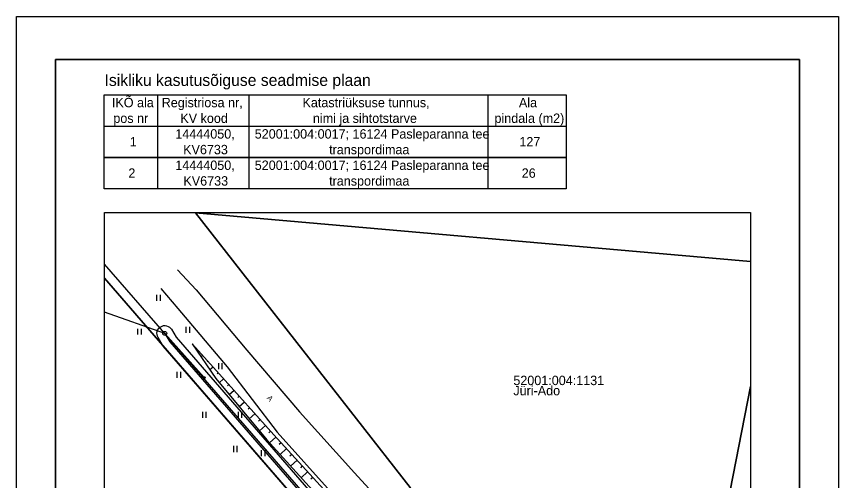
# Model space of a CAD drawing. Extents: x 469301 to 469406, y 6542150 to 6542298.
# Drawn here: x 469300.9 to 469405.9, y 6542239 to 6542298.2 of the extents above; entities that cross this region are included whole.
import ezdxf

# ---------------------------------------------------------------- set-up
doc = ezdxf.new("R2010")
doc.units = 0
for name, color, linetype in [('HALJASTUS', 7, 'Continuous'), ('KASUTUSALA', 7, 'Continuous'), ('KPOHULIIN', 7, 'Continuous'), ('MADALPINGE', 7, 'Continuous'), ('MPOHULIIN', 7, 'Continuous'), ('PIIR', 7, 'Continuous'), ('POST', 7, 'Continuous'), ('RELJEEF', 7, 'Continuous'), ('TEE', 7, 'Continuous'), ('VORMISTUS', 7, 'Continuous')]:
    doc.layers.add(name, color=color, linetype=linetype)

msp = doc.modelspace()

# ---------------------------------------------------------------- linework, layer by layer
at = {"layer": 'HALJASTUS'}
for p, q in [((469318.79, 6542262.67), (469318.79, 6542261.91)), ((469319.25, 6542262.67), (469319.25, 6542261.91)), ((469316.36, 6542258.34), (469316.36, 6542257.58)), ((469316.82, 6542258.34), (469316.82, 6542257.58)), ((469322.54, 6542258.57), (469322.54, 6542257.81)), ((469323, 6542258.57), (469323, 6542257.81)), ((469326.68, 6542253.92), (469326.68, 6542253.16)), ((469327.13, 6542253.92), (469327.13, 6542253.16)), ((469321.39, 6542252.84), (469321.39, 6542252.07)), ((469321.85, 6542252.84), (469321.85, 6542252.07)), ((469324.63, 6542247.72), (469324.63, 6542246.96)), ((469325.09, 6542247.72), (469325.09, 6542246.96)), ((469329.19, 6542247.74), (469329.19, 6542246.98)), ((469329.65, 6542247.74), (469329.65, 6542246.98)), ((469328.6, 6542243.37), (469328.6, 6542242.6)), ((469329.05, 6542243.37), (469329.05, 6542242.6)), ((469332.14, 6542242.83), (469332.14, 6542242.07)), ((469332.59, 6542242.83), (469332.59, 6542242.07))]:
    msp.add_line(p, q, dxfattribs=at)
at = {"layer": 'KASUTUSALA'}
msp.add_lwpolyline([(469342.49, 6542229.78), (469319.64, 6542256.12), (469318.97, 6542257.22), (469318.89, 6542257.4), (469318.84, 6542257.59), (469318.83, 6542257.78), (469318.86, 6542257.98), (469318.92, 6542258.16), (469319.02, 6542258.33), (469319.15, 6542258.48), (469319.31, 6542258.59), (469319.49, 6542258.68), (469319.68, 6542258.73), (469319.87, 6542258.74), (469320.07, 6542258.71), (469320.25, 6542258.64), (469320.42, 6542258.54), (469320.57, 6542258.41), (469320.68, 6542258.26), (469321.28, 6542257.27), (469344.29, 6542230.75)], dxfattribs=at)
at = {"layer": 'KPOHULIIN'}
msp.add_lwpolyline([(469394.64, 6542171.86), (469371.98, 6542197.83), (469319.83, 6542257.74), (469312.14, 6542266.58)], dxfattribs=at)
at = {"layer": 'MADALPINGE'}
msp.add_lwpolyline([(469319.83, 6542257.74), (469320.47, 6542256.68), (469343.57, 6542230.06), (469351.22, 6542222.88), (469355.02, 6542218.97), (469360.25, 6542214.09), (469364.35, 6542209.32), (469365.78, 6542207.16), (469367.06, 6542205.43), (469381.93, 6542191.51), (469382.88, 6542190.67)], dxfattribs=at)
at = {"layer": 'MPOHULIIN'}
msp.add_line((469319.83, 6542257.74), (469312.14, 6542260.43), dxfattribs=at)
at = {"layer": 'PIIR'}
for points in [[(469323.7, 6542273.19), (469323.75, 6542273.13), (469323.73, 6542273.19)], [(469394.64, 6542197.37), (469385.71, 6542205.29), (469351.18, 6542238.06), (469323.75, 6542273.13), (469323.7, 6542273.19)], [(469323.73, 6542273.19), (469323.75, 6542273.13), (469394.64, 6542266.9)], [(469394.64, 6542266.9), (469323.75, 6542273.13), (469351.18, 6542238.06), (469385.71, 6542205.29), (469394.64, 6542250.96)], [(469312.14, 6542264.77), (469342.49, 6542229.78), (469383.02, 6542191.86), (469394.64, 6542181.77)], [(469329.57, 6542168.19), (469342.49, 6542229.78), (469312.14, 6542264.77)], [(469394.64, 6542250.96), (469385.71, 6542205.29), (469394.64, 6542197.37)]]:
    msp.add_lwpolyline(points, dxfattribs=at)
at = {"layer": 'POST'}
msp.add_lwpolyline([(469324.88, 6542252.09), (469319.83, 6542257.74)], dxfattribs=at)
for centre, radius in [((469319.83, 6542257.74), 0.25), ((469319.83, 6542257.74), 0.0234), ((469324.88, 6542252.09), 0.125), ((469324.88, 6542252.09), 0.105), ((469324.88, 6542252.09), 0.0851), ((469324.88, 6542252.09), 0.0651), ((469324.88, 6542252.09), 0.0451), ((469324.88, 6542252.09), 0.0251), ((469324.88, 6542252.09), 0.00511)]:
    msp.add_circle(centre, radius, dxfattribs=at)
at = {"layer": 'RELJEEF'}
for p, q in [((469324, 6542255.67), (469323.97, 6542255.64)), ((469324.67, 6542254.93), (469324.47, 6542254.74)), ((469325.34, 6542254.19), (469325.25, 6542254.1)), ((469326.01, 6542253.45), (469325.6, 6542253.07)), ((469326.68, 6542252.71), (469326.53, 6542252.57)), ((469327.35, 6542251.96), (469326.78, 6542251.45)), ((469328.02, 6542251.21), (469327.84, 6542251.06)), ((469328.68, 6542250.47), (469328.06, 6542249.92)), ((469329.35, 6542249.72), (469329.16, 6542249.55)), ((469330.02, 6542248.98), (469329.35, 6542248.38)), ((469330.68, 6542248.23), (469330.47, 6542248.05)), ((469331.35, 6542247.49), (469330.63, 6542246.84)), ((469332.01, 6542246.74), (469331.79, 6542246.54)), ((469332.68, 6542245.99), (469331.91, 6542245.31)), ((469333.35, 6542245.25), (469333.11, 6542245.04)), ((469334.02, 6542244.51), (469333.22, 6542243.77)), ((469334.69, 6542243.77), (469334.45, 6542243.55)), ((469335.37, 6542243.03), (469334.56, 6542242.29)), ((469336.05, 6542242.3), (469335.8, 6542242.07)), ((469336.72, 6542241.56), (469335.9, 6542240.8)), ((469337.4, 6542240.82), (469337.15, 6542240.59)), ((469338.07, 6542240.09), (469337.24, 6542239.32)), ((469338.75, 6542239.35), (469338.5, 6542239.12))]:
    msp.add_line(p, q, dxfattribs=at)
for points in [[(469323.33, 6542256.41), (469326.83, 6542252.55), (469333.75, 6542244.79), (469341.09, 6542236.8), (469348.8, 6542228.55), (469356.72, 6542220.92), (469360.28, 6542217.48), (469366.26, 6542211.29), (469372.66, 6542205.96), (469379.32, 6542199.72), (469381.68, 6542197.49), (469387.45, 6542192.09)], [(469323.33, 6542256.41), (469326.35, 6542251.97), (469332.88, 6542244.14), (469340.34, 6542235.9), (469348.12, 6542227.74), (469355.84, 6542219.92), (469359.64, 6542216.74), (469365.45, 6542210.12), (469365.99, 6542208.97), (469366.96, 6542207.94), (469368.26, 6542208.16), (469371.79, 6542205), (469377.98, 6542198.3), (469380.12, 6542196.03), (469386.79, 6542189.81)]]:
    msp.add_lwpolyline(points, dxfattribs=at)
at = {"layer": 'TEE'}
for points in [[(469321.47, 6542265.87), (469323.83, 6542263.28), (469330.32, 6542255.61), (469337.05, 6542247.73), (469344.07, 6542239.95), (469351.96, 6542231.33), (469359.24, 6542224.01), (469363.1, 6542220.41), (469368.89, 6542214.95), (469375.21, 6542209.34), (469380.21, 6542205.01), (469384.74, 6542200.79), (469384.8, 6542200.07), (469388.51, 6542196.65)], [(469319.32, 6542263.48), (469321.5, 6542260.92), (469327.79, 6542253.47), (469334.18, 6542245.15), (469341.4, 6542237.13), (469349.23, 6542228.84), (469356.95, 6542221.19), (469360.43, 6542217.78), (469366.66, 6542212.03), (469373.02, 6542206.41), (469378.05, 6542201.72), (469379.93, 6542200.17), (469379.92, 6542199.58), (469381.55, 6542198.02), (469382, 6542198.27), (469387.69, 6542193.14)]]:
    msp.add_lwpolyline(points, dxfattribs=at)
at = {"layer": 'VORMISTUS'}
for p, q in [((469318.91, 6542288.2), (469318.91, 6542280.2)), ((469330.56, 6542288.2), (469330.56, 6542280.2)), ((469361.11, 6542288.2), (469361.11, 6542280.2)), ((469312.11, 6542284.2), (469371.11, 6542284.2)), ((469312.11, 6542280.2), (469371.11, 6542280.2)), ((469318.91, 6542280.2), (469318.91, 6542276.2)), ((469330.56, 6542280.2), (469330.56, 6542276.2)), ((469361.11, 6542280.2), (469361.11, 6542276.2))]:
    msp.add_line(p, q, dxfattribs=at)
for points in [[(469300.89, 6542298.19), (469405.89, 6542298.19), (469405.89, 6542149.69), (469300.89, 6542149.69)], [(469305.89, 6542155.19), (469400.89, 6542155.19), (469400.89, 6542292.69), (469305.89, 6542292.69)], [(469305.89, 6542292.69), (469400.89, 6542292.69), (469400.89, 6542155.19), (469305.89, 6542155.19)], [(469312.11, 6542288.2), (469371.11, 6542288.2), (469371.11, 6542280.2), (469312.11, 6542280.2)], [(469312.11, 6542280.2), (469371.11, 6542280.2), (469371.11, 6542276.2), (469312.11, 6542276.2)], [(469394.64, 6542168.19), (469312.14, 6542168.19), (469312.14, 6542273.19), (469394.64, 6542273.19)]]:
    msp.add_lwpolyline(points, close=True, dxfattribs=at)

# ---------------------------------------------------------------- texts
at = {"layer": 'PIIR'}
for s, p in [('52001:004:1131', (469364.35, 6542251.14)), ('Jüri-Ado', (469364.35, 6542249.84))]:
    msp.add_text(s, height=1.2, dxfattribs=at).set_placement(p)
at = {"layer": 'TEE'}
msp.add_text('A', height=0.7, rotation=311.4802, dxfattribs=at).set_placement((469332.8, 6542249.46))
at = {"layer": 'VORMISTUS'}
for s, height, p in [('Isikliku kasutusõiguse seadmise plaan', 1.5, (469312.14, 6542289.32)), ('IKÕ ala', 1.2, (469313.08, 6542286.6)), ('Registriosa nr,', 1.2, (469319.44, 6542286.6)), ('Katastriüksuse tunnus,', 1.2, (469337.42, 6542286.6)), ('Ala', 1.2, (469365.06, 6542286.6)), ('pos nr', 1.2, (469313.26, 6542284.6)), ('KV kood', 1.2, (469321.82, 6542284.6)), ('nimi ja sihtotstarve', 1.2, (469338.75, 6542284.6)), ('pindala (m2)', 1.2, (469361.94, 6542284.6)), ('14444050,', 1.2, (469321.18, 6542282.6)), ('52001:004:0017; 16124 Pasleparanna tee', 1.2, (469331.32, 6542282.6)), ('1', 1.2, (469315.36, 6542281.6)), ('127', 1.2, (469365.12, 6542281.6)), ('KV6733', 1.2, (469322.18, 6542280.6)), ('transpordimaa', 1.2, (469340.82, 6542280.6)), ('14444050,', 1.2, (469321.18, 6542278.6)), ('52001:004:0017; 16124 Pasleparanna tee', 1.2, (469331.32, 6542278.6)), ('2', 1.2, (469315.18, 6542277.6)), ('26', 1.2, (469365.42, 6542277.6)), ('KV6733', 1.2, (469322.21, 6542276.6)), ('transpordimaa', 1.2, (469340.82, 6542276.6))]:
    msp.add_text(s, height=height, dxfattribs=at).set_placement(p)

doc.saveas('drawing.dxf')
